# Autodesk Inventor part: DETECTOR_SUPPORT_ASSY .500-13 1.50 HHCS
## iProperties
Shininess: 64.0
Length Units: 11272
Angle Units: 11279
Time Units: 11290
Mass Units: 11286
Length Display Precision: 3
Angle Display Precision: 2
Compacted: True
Part Number: DETECTOR_SUPPORT_ASSY .500-13 1.50 HHCS
Document SubType Name: Modeling
Created: 2004-08
Designer: John Blackburn
Material: MILD_STEEL
Manufacturer: Standard
Standards Organization: Custom
Density: 0.0
Volumn: 0.0
Area: 0.0
PropertySet Name: Model Information
Control State: 0
Master: False
Checked Out: False
Author: John Blackburn
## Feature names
1. Base1
